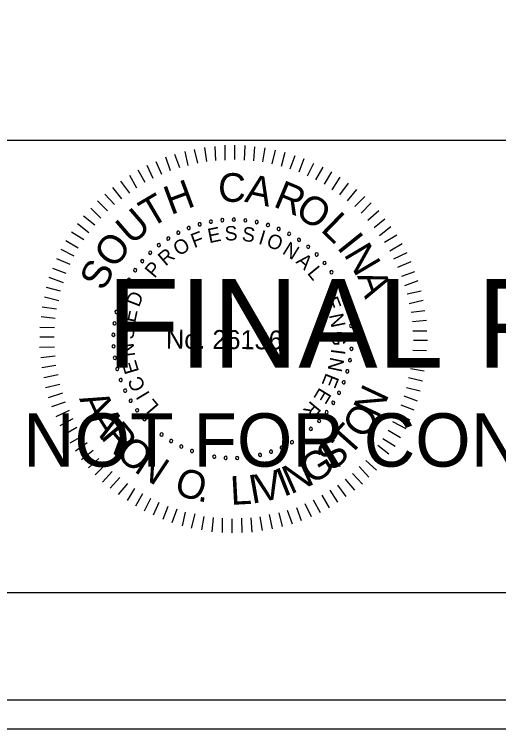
# Model space of a CAD drawing. Extents: x 967 to 1326, y 964 to 3144.
# Drawn here: x 1170.56 to 1189.3, y 1523.72 to 1551.36 of the extents above; entities that cross this region are included whole.
import ezdxf

# ---------------------------------------------------------------- set-up
doc = ezdxf.new("R2010")
doc.units = 0
for name, color, linetype in [('RD_XS_EwShp', 7, 'Continuous'), ('RD_XS_ExPaveRet', 7, 'Continuous'), ('RD_XS_TX_Elev_EX', 7, 'Continuous'), ('RD_XS_TX_Elev_PR', 7, 'Continuous'), ('RD_XS_TX_Station', 7, 'Continuous')]:
    doc.layers.add(name, color=color, linetype=linetype)

msp = doc.modelspace()

# ---------------------------------------------------------------- linework, layer by layer
at = {"layer": 'RD_XS_ExPaveRet'}
for points in [[(967.409, 1523.72), (1326.285, 1523.72), (1326.285, 1743.72), (967.409, 1743.72)], [(988.525, 1524.84), (1326.285, 1524.84), (1326.285, 1742.6), (988.525, 1742.6)]]:
    msp.add_lwpolyline(points, close=True, dxfattribs=at)
at = {"layer": 'RD_XS_TX_Elev_EX'}
for p, q in [((996.114, 1546.486), (1323.886, 1546.486)), ((1323.886, 1528.983), (996.114, 1528.983))]:
    msp.add_line(p, q, dxfattribs=at)
at = {"layer": 'RD_XS_TX_Elev_PR'}
for p, q in [((1178.01, 1545.663), (1177.93, 1546.209)), ((1178.364, 1545.699), (1178.33, 1546.244)), ((1178.717, 1545.719), (1178.722, 1546.295)), ((1179.093, 1545.739), (1179.098, 1546.292)), ((1179.469, 1545.713), (1179.489, 1546.288)), ((1179.829, 1545.687), (1179.872, 1546.231)), ((1180.174, 1545.646), (1180.271, 1546.19)), ((1176.964, 1545.419), (1176.769, 1545.935)), ((1177.287, 1545.508), (1177.169, 1546.054)), ((1177.657, 1545.597), (1177.53, 1546.128)), ((1180.535, 1545.573), (1180.662, 1546.102)), ((1180.902, 1545.478), (1181.045, 1546.022)), ((1181.231, 1545.384), (1181.428, 1545.896)), ((1176.264, 1545.156), (1176.053, 1545.657)), ((1176.61, 1545.306), (1176.423, 1545.83)), ((1181.584, 1545.265), (1181.78, 1545.786)), ((1175.933, 1545.005), (1175.699, 1545.506)), ((1181.905, 1545.109), (1182.154, 1545.606)), ((1182.226, 1544.953), (1182.506, 1545.45)), ((1175.308, 1544.634), (1175.036, 1545.12)), ((1175.624, 1544.846), (1175.352, 1545.332)), ((1182.562, 1544.789), (1182.85, 1545.27)), ((1175.03, 1544.445), (1174.681, 1544.9)), ((1182.86, 1544.572), (1183.163, 1545.053)), ((1183.158, 1544.378), (1183.484, 1544.828)), ((1174.729, 1544.217), (1174.372, 1544.665)), ((1183.447, 1544.145), (1183.811, 1544.587)), ((1174.435, 1543.997), (1174.062, 1544.399)), ((1183.729, 1543.92), (1184.116, 1544.316)), ((1174.172, 1543.753), (1173.776, 1544.148)), ((1183.98, 1543.672), (1184.368, 1544.061)), ((1173.909, 1543.479), (1173.52, 1543.858)), ((1184.232, 1543.394), (1184.657, 1543.767)), ((1173.684, 1543.197), (1173.242, 1543.546)), ((1184.475, 1543.108), (1184.892, 1543.45)), ((1173.451, 1542.9), (1173.009, 1543.256)), ((1184.687, 1542.807), (1185.128, 1543.156)), ((1173.257, 1542.64), (1172.776, 1542.936)), ((1173.039, 1542.312), (1172.559, 1542.6)), ((1184.885, 1542.544), (1185.355, 1542.832)), ((1185.081, 1542.213), (1185.56, 1542.493)), ((1172.883, 1542.006), (1172.379, 1542.256)), ((1185.24, 1541.904), (1185.756, 1542.145)), ((1172.727, 1541.677), (1172.215, 1541.904)), ((1185.399, 1541.573), (1185.907, 1541.791)), ((1172.571, 1541.333), (1172.051, 1541.53)), ((1185.549, 1541.226), (1186.057, 1541.414)), ((1172.461, 1540.974), (1171.91, 1541.178)), ((1185.669, 1540.865), (1186.185, 1541.06)), ((1172.351, 1540.652), (1171.807, 1540.787)), ((1185.759, 1540.541), (1186.297, 1540.667)), ((1172.286, 1540.276), (1171.727, 1540.419)), ((1185.832, 1540.165), (1186.371, 1540.298)), ((1172.191, 1539.955), (1171.647, 1540.029)), ((1185.906, 1539.842), (1186.436, 1539.906)), ((1172.15, 1539.587), (1171.598, 1539.653)), ((1185.964, 1539.473), (1186.51, 1539.53)), ((1172.124, 1539.234), (1171.548, 1539.239)), ((1185.977, 1539.12), (1186.514, 1539.115)), ((1172.105, 1538.866), (1171.545, 1538.871)), ((1185.997, 1538.751), (1186.542, 1538.747)), ((1172.118, 1538.482), (1171.542, 1538.471)), ((1185.971, 1538.368), (1186.508, 1538.348)), ((1172.138, 1538.136), (1171.585, 1538.072)), ((1185.952, 1538.022), (1186.497, 1537.949)), ((1172.173, 1537.768), (1171.627, 1537.688)), ((1185.888, 1537.655), (1186.417, 1537.566)), ((1172.262, 1537.414), (1171.701, 1537.296)), ((1185.808, 1537.302), (1186.345, 1537.175)), ((1172.321, 1537.037), (1171.774, 1536.911)), ((1185.729, 1536.926), (1186.265, 1536.792)), ((1172.425, 1536.707), (1171.871, 1536.519)), ((1185.634, 1536.597), (1186.146, 1536.401)), ((1172.53, 1536.36), (1172.007, 1536.173)), ((1185.508, 1536.253), (1186.013, 1536.057)), ((1172.681, 1536.029), (1172.165, 1535.788)), ((1172.831, 1535.705), (1172.323, 1535.441)), ((1185.352, 1535.924), (1185.857, 1535.675)), ((1185.188, 1535.603), (1185.7, 1535.33)), ((1172.982, 1535.374), (1172.497, 1535.094)), ((1185.024, 1535.274), (1185.498, 1534.987)), ((1173.194, 1535.042), (1172.709, 1534.762)), ((1184.822, 1534.946), (1185.288, 1534.658)), ((1173.384, 1534.78), (1172.936, 1534.453)), ((1184.62, 1534.687), (1185.055, 1534.353)), ((1173.612, 1534.478), (1173.164, 1534.129)), ((1184.403, 1534.389), (1184.814, 1534.033)), ((1173.832, 1534.177), (1173.437, 1533.812)), ((1184.155, 1534.092), (1184.574, 1533.72)), ((1174.091, 1533.945), (1173.689, 1533.541)), ((1183.899, 1533.864), (1184.28, 1533.454)), ((1174.35, 1533.674), (1173.97, 1533.263)), ((1183.644, 1533.597), (1184.024, 1533.18)), ((1174.64, 1533.442), (1174.275, 1533.022)), ((1174.937, 1533.209), (1174.58, 1532.782)), ((1183.358, 1533.37), (1183.715, 1532.944)), ((1175.212, 1533.014), (1174.932, 1532.549)), ((1182.764, 1532.952), (1183.059, 1532.482)), ((1183.065, 1533.141), (1183.384, 1532.709)), ((1175.525, 1532.812), (1175.245, 1532.331)), ((1175.83, 1532.633), (1175.588, 1532.136)), ((1182.463, 1532.755), (1182.743, 1532.269)), ((1176.159, 1532.477), (1175.94, 1531.98)), ((1181.8, 1532.431), (1182.041, 1531.93)), ((1182.124, 1532.581), (1182.396, 1532.08)), ((1176.503, 1532.321), (1176.307, 1531.816)), ((1176.855, 1532.211), (1176.651, 1531.69)), ((1177.177, 1532.1), (1177.05, 1531.572)), ((1181.122, 1532.175), (1181.31, 1531.652)), ((1181.476, 1532.28), (1181.664, 1531.771)), ((1177.545, 1532.036), (1177.409, 1531.484)), ((1177.897, 1531.933), (1177.808, 1531.412)), ((1178.25, 1531.892), (1178.207, 1531.34)), ((1178.603, 1531.866), (1178.598, 1531.313)), ((1178.978, 1531.84), (1178.974, 1531.295)), ((1179.355, 1531.86), (1179.365, 1531.307)), ((1179.715, 1531.88), (1179.749, 1531.327)), ((1180.061, 1531.915), (1180.149, 1531.393)), ((1180.423, 1532.012), (1180.541, 1531.458)), ((1180.791, 1532.07), (1180.926, 1531.54))]:
    msp.add_line(p, q, dxfattribs=at)
for centre, start, end in [((1178.609, 1543.397), 5.0653, 185.0653), ((1179.055, 1543.414), 359.5268, 179.5268), ((1179.055, 1543.414), 179.5268, 359.5268), ((1179.5, 1543.388), 353.9884, 173.9884), ((1177.312, 1543.091), 21.6807, 201.6807), ((1177.734, 1543.235), 16.1422, 196.1422), ((1177.734, 1543.235), 196.1422, 16.1422), ((1178.168, 1543.337), 10.6038, 190.6038), ((1178.168, 1543.337), 190.6038, 10.6038), ((1178.609, 1543.397), 185.0653, 5.0653), ((1179.5, 1543.388), 173.9884, 353.9884), ((1179.94, 1543.319), 168.4499, 348.4499), ((1179.94, 1543.319), 348.4499, 168.4499), ((1180.372, 1543.208), 162.9114, 342.9114), ((1180.372, 1543.208), 342.9114, 162.9114), ((1176.906, 1542.908), 27.2191, 207.2191), ((1176.906, 1542.908), 207.2191, 27.2191), ((1177.312, 1543.091), 201.6807, 21.6807), ((1180.79, 1543.056), 157.373, 337.373), ((1180.79, 1543.056), 337.373, 157.373), ((1181.193, 1542.864), 151.8345, 331.8345), ((1181.193, 1542.864), 331.8345, 151.8345), ((1176.52, 1542.686), 32.7576, 212.7576), ((1176.52, 1542.686), 212.7576, 32.7576), ((1181.574, 1542.634), 146.2961, 326.2961), ((1181.574, 1542.634), 326.2961, 146.2961), ((1176.156, 1542.428), 38.2961, 218.2961), ((1176.156, 1542.428), 218.2961, 38.2961), ((1181.932, 1542.368), 140.7576, 320.7576), ((1181.932, 1542.368), 320.7576, 140.7576), ((1175.82, 1542.135), 43.8345, 223.8345), ((1175.82, 1542.135), 223.8345, 43.8345), ((1182.263, 1542.069), 135.2191, 315.2191), ((1182.263, 1542.069), 315.2191, 135.2191), ((1175.513, 1541.812), 49.373, 229.373), ((1175.513, 1541.812), 229.373, 49.373), ((1182.563, 1541.74), 129.6807, 309.6807), ((1182.563, 1541.74), 309.6807, 129.6807), ((1175.239, 1541.461), 54.9114, 234.9114), ((1175.239, 1541.461), 234.9114, 54.9114), ((1182.83, 1541.383), 124.1422, 304.1422), ((1182.83, 1541.383), 304.1422, 124.1422), ((1175, 1541.085), 60.4499, 240.4499), ((1175, 1541.085), 240.4499, 60.4499), ((1183.061, 1541.002), 118.6038, 298.6038), ((1183.061, 1541.002), 298.6038, 118.6038), ((1174.798, 1540.687), 65.9884, 245.9884), ((1174.798, 1540.687), 245.9884, 65.9884), ((1183.255, 1540.601), 113.0653, 293.0653), ((1183.255, 1540.601), 293.0653, 113.0653), ((1174.636, 1540.272), 71.5268, 251.5268), ((1174.636, 1540.272), 251.5268, 71.5268), ((1183.408, 1540.182), 107.5268, 287.5268), ((1183.408, 1540.182), 287.5268, 107.5268), ((1174.514, 1539.843), 77.0653, 257.0653), ((1174.514, 1539.843), 257.0653, 77.0653), ((1183.521, 1539.751), 101.9884, 281.9884), ((1183.521, 1539.751), 281.9884, 101.9884), ((1174.435, 1539.405), 82.6038, 262.6038), ((1174.435, 1539.405), 262.6038, 82.6038), ((1183.592, 1539.311), 96.4499, 276.4499), ((1183.592, 1539.311), 276.4499, 96.4499), ((1174.398, 1538.961), 88.1422, 268.1422), ((1174.398, 1538.961), 268.1422, 88.1422), ((1183.619, 1538.866), 90.9114, 270.9114), ((1183.619, 1538.866), 270.9114, 90.9114), ((1174.404, 1538.515), 93.6807, 273.6807), ((1174.404, 1538.515), 273.6807, 93.6807), ((1183.604, 1538.421), 85.373, 265.373), ((1183.604, 1538.421), 265.373, 85.373), ((1174.453, 1538.072), 99.2191, 279.2191), ((1174.453, 1538.072), 279.2191, 99.2191), ((1183.546, 1537.979), 79.8345, 259.8345), ((1183.546, 1537.979), 259.8345, 79.8345), ((1174.545, 1537.636), 104.7576, 284.7576), ((1174.545, 1537.636), 284.7576, 104.7576), ((1183.445, 1537.545), 74.2961, 254.2961), ((1183.445, 1537.545), 254.2961, 74.2961), ((1174.678, 1537.211), 110.2961, 290.2961), ((1174.678, 1537.211), 290.2961, 110.2961), ((1183.303, 1537.122), 68.7576, 248.7576), ((1183.303, 1537.122), 248.7576, 68.7576), ((1174.852, 1536.8), 115.8345, 295.8345), ((1174.852, 1536.8), 295.8345, 115.8345), ((1183.121, 1536.716), 63.2191, 243.2191), ((1183.121, 1536.716), 243.2191, 63.2191), ((1175.065, 1536.409), 121.373, 301.373), ((1175.065, 1536.409), 301.373, 121.373), ((1182.9, 1536.328), 57.6807, 237.6807), ((1182.9, 1536.328), 237.6807, 57.6807), ((1175.314, 1536.039), 126.9114, 306.9114), ((1175.314, 1536.039), 306.9114, 126.9114), ((1182.643, 1535.964), 52.1422, 232.1422), ((1182.643, 1535.964), 232.1422, 52.1422), ((1175.598, 1535.696), 132.4499, 312.4499), ((1175.598, 1535.696), 312.4499, 132.4499), ((1182.353, 1535.627), 46.6038, 226.6038), ((1182.353, 1535.627), 226.6038, 46.6038), ((1175.914, 1535.381), 137.9884, 317.9884), ((1175.914, 1535.381), 317.9884, 137.9884), ((1176.258, 1535.099), 143.5268, 323.5268), ((1176.258, 1535.099), 323.5268, 143.5268), ((1182.03, 1535.319), 41.0653, 221.0653), ((1182.03, 1535.319), 221.0653, 41.0653), ((1176.629, 1534.851), 149.0653, 329.0653), ((1176.629, 1534.851), 329.0653, 149.0653), ((1181.305, 1534.803), 29.9884, 209.9884), ((1181.68, 1535.043), 35.5268, 215.5268), ((1181.68, 1535.043), 215.5268, 35.5268), ((1177.021, 1534.639), 154.6038, 334.6038), ((1177.021, 1534.639), 334.6038, 154.6038), ((1180.908, 1534.6), 24.4499, 204.4499), ((1180.908, 1534.6), 204.4499, 24.4499), ((1181.305, 1534.803), 209.9884, 29.9884), ((1177.432, 1534.467), 160.1422, 340.1422), ((1177.432, 1534.467), 340.1422, 160.1422), ((1177.858, 1534.335), 165.6807, 345.6807), ((1177.858, 1534.335), 345.6807, 165.6807), ((1178.294, 1534.245), 351.2191, 171.2191), ((1179.627, 1534.232), 7.8345, 187.8345), ((1180.065, 1534.313), 13.373, 193.373), ((1180.065, 1534.313), 193.373, 13.373), ((1180.494, 1534.436), 18.9114, 198.9114), ((1180.494, 1534.436), 198.9114, 18.9114), ((1178.294, 1534.245), 171.2191, 351.2191), ((1178.737, 1534.198), 356.7576, 176.7576), ((1178.737, 1534.198), 176.7576, 356.7576), ((1179.183, 1534.193), 2.2961, 182.2961), ((1179.183, 1534.193), 182.2961, 2.2961), ((1179.627, 1534.232), 187.8345, 7.8345)]:
    msp.add_arc(centre, 0.0627, start, end, dxfattribs=at)
at = {"layer": 'RD_XS_TX_Station'}
msp.add_lwpolyline([(967.409, 1523.72), (1326.285, 1523.72), (1326.285, 1743.72), (967.409, 1743.72)], close=True, dxfattribs=at)

# ---------------------------------------------------------------- texts
at = {"layer": 'RD_XS_EwShp'}
for s, height, p in [('FINAL PLANS', 3.4375, (1174.145, 1537.685)), ('NOT FOR CONSTRUCTION', 2.0625, (1170.901, 1533.86))]:
    msp.add_text(s, height=height, dxfattribs=at).set_placement(p)
at = {"layer": 'RD_XS_TX_Elev_PR'}
for s, height, rotation, p in [('C', 1.11, 359.5482, (1178.442, 1544.108)), ('A', 1.11, 348.1981, (1179.439, 1544.115)), ('H', 1.11, 20.3637, (1176.614, 1543.587)), ('R', 1.11, 337.4344, (1180.541, 1543.937)), ('T', 1.11, 30.4992, (1175.828, 1543.072)), ('O', 1.108, 326.5869, (1181.366, 1543.609)), ('U', 1.11, 40.8022, (1175.102, 1542.403)), ('L', 1.11, 315.9488, (1182.373, 1543.003)), ('E', 0.557, 11.4103, (1178.103, 1542.503)), ('S', 0.557, 2.208, (1178.709, 1542.601)), ('S', 0.557, 352.6608, (1179.346, 1542.599)), ('F', 0.557, 20.6127, (1177.52, 1542.309)), ('I', 0.557, 343.1136, (1179.975, 1542.491)), ('O', 0.557, 338.4392, (1180.274, 1542.401)), ('I', 1.11, 308.6613, (1183.011, 1542.338)), ('O', 1.11, 52.0267, (1174.435, 1541.474)), ('O', 0.557, 30.8477, (1176.917, 1541.987)), ('N', 0.557, 328.2042, (1180.896, 1542.12)), ('N', 1.11, 300.7037, (1183.285, 1542.075)), ('R', 0.557, 40.3949, (1176.415, 1541.594)), ('A', 0.557, 318.657, (1181.424, 1541.762)), ('S', 1.108, 63.2511, (1174.029, 1540.619)), ('P', 0.557, 49.9421, (1175.985, 1541.124)), ('L', 0.557, 309.4546, (1181.869, 1541.339)), ('A', 1.11, 289.4792, (1183.814, 1541.243)), ('D', 0.557, 69.0364, (1175.386, 1540.003)), ('E', 0.557, 291.049, (1182.53, 1540.307)), ('E', 0.557, 78.2388, (1175.238, 1539.407)), ('N', 0.557, 281.8466, (1182.728, 1539.726)), ('S', 0.557, 87.786, (1175.187, 1538.772)), ('No. 26136', 0.7311, 359.5268, (1176.429, 1538.43)), ('G', 0.557, 272.2995, (1182.833, 1539.097)), ('N', 0.557, 97.3332, (1175.242, 1538.137)), ('I', 0.557, 262.4084, (1182.83, 1538.437)), ('E', 0.557, 106.5355, (1175.394, 1537.541)), ('N', 0.557, 257.7339, (1182.789, 1538.127)), ('C', 0.557, 116.4266, (1175.661, 1536.938)), ('E', 0.557, 248.1867, (1182.628, 1537.511)), ('I', 0.557, 121.1011, (1175.823, 1536.67)), ('E', 0.557, 238.9844, (1182.378, 1536.949)), ('N', 1.105, 64.8922, (1184.632, 1535.684)), ('A', 1.105, 294.7297, (1173.062, 1536.486)), ('L', 0.557, 129.9595, (1176.187, 1536.204)), ('R', 0.557, 229.782, (1182.041, 1536.435)), ('O', 1.105, 56.2059, (1184.102, 1534.874)), ('A', 1.105, 302.2892, (1173.414, 1535.72)), ('R', 1.105, 309.8487, (1173.865, 1535.007)), ('T', 1.105, 48.2685, (1183.515, 1534.211)), ('O', 1.105, 317.7861, (1174.434, 1534.33)), ('S', 1.105, 40.3311, (1182.842, 1533.636)), ('N', 1.105, 326.4725, (1175.158, 1533.686)), ('G', 1.105, 32.0198, (1182.059, 1533.14)), ('N', 1.105, 24.0824, (1181.252, 1532.776)), ('O', 1.105, 342.3472, (1176.697, 1532.82)), ('V', 1.105, 12.7741, (1180.033, 1532.457)), ('I', 1.105, 21.4605, (1180.976, 1532.681)), ('L', 1.105, 2.9677, (1178.943, 1532.379)), ('I', 1.105, 10.1523, (1179.743, 1532.418)), ('.', 1.105, 351.0336, (1177.623, 1532.536))]:
    msp.add_text(s, height=height, rotation=rotation, dxfattribs=at).set_placement(p)

doc.saveas('drawing.dxf')
